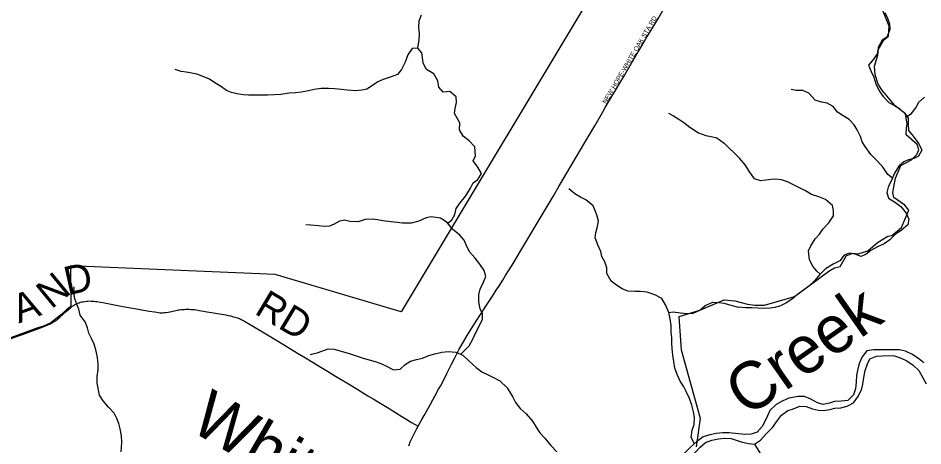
# Model space of a CAD drawing. Extents: x 1451455 to 1749751, y 218250 to 574981.
# Drawn here: x 1570249 to 1579778, y 367778 to 372287 of the extents above; entities that cross this region are included whole.
import ezdxf

# ---------------------------------------------------------------- set-up
doc = ezdxf.new("R2010")
doc.units = 0
for name, color, linetype in [('GM_X_City_Street', 7, 'Continuous'), ('GM_X_City_Street_Text', 7, 'Continuous'), ('GM_X_Corporation', 7, 'Continuous'), ('GM_X_County_Road', 7, 'Continuous'), ('GM_X_County_Road_Text', 7, 'Continuous'), ('GM_X_Major_River', 7, 'Continuous'), ('GM_X_Major_River_Text', 7, 'Continuous'), ('GM_X_Minor_River', 7, 'Continuous'), ('GM_X_Township', 7, 'Continuous')]:
    doc.layers.add(name, color=color, linetype=linetype)

msp = doc.modelspace()

# ---------------------------------------------------------------- linework, layer by layer
at = {"layer": 'GM_X_City_Street'}
msp.add_lwpolyline([(1576403.2, 371290.5), (1576433.5, 371342.8), (1576627.5, 371672), (1576696.7, 371787.7), (1576769.1, 371911.8), (1576787.8, 371943.4), (1576847.5, 372043.6), (1576865.4, 372074), (1576933.3, 372185.8), (1576996.4, 372293.8), (1577086.1, 372448.5), (1577119, 372505.8), (1577147.9, 372555.6), (1577156.9, 372571.7), (1577177.1, 372609.6), (1577191.9, 372638.4), (1577203.5, 372664.9), (1577210.3, 372682.1), (1577217.3, 372700.6), (1577222.8, 372716.8), (1577226.9, 372730.2), (1577232.6, 372751.3), (1577236.4, 372767), (1577237.7, 372774.9)], dxfattribs=at)
at = {"layer": 'GM_X_Corporation'}
msp.add_lwpolyline([(1569813.3, 375725.6), (1574235.6, 374596.8), (1575127.2, 374369.7), (1576500.8, 372892.2), (1574283.4, 369191.6), (1572956.4, 369585.2), (1570803, 369677.4), (1570805.4, 369246.2), (1570764.4, 369217.1), (1570697.9, 369158.2), (1570643.5, 369113.5), (1570593, 369073.7), (1570517.3, 369040.5), (1570456.2, 369021.9), (1569964.8, 368843.9)], dxfattribs=at)
at = {"layer": 'GM_X_County_Road'}
for points in [[(1574462.3, 367985.2), (1574505.6, 368063), (1574525.2, 368097.7), (1574570.5, 368180.2), (1574638.9, 368303.4), (1574678, 368374.8), (1574696.7, 368409.4), (1574732.3, 368475.8), (1574765.5, 368542.6), (1574793.4, 368598.8), (1574813.3, 368639.1), (1574844.2, 368700.5), (1574891.2, 368790.3), (1574928.3, 368856.2), (1574990.6, 368960.4), (1575049.4, 369055.3), (1575111.7, 369151.8), (1575183.6, 369261.5), (1575238.7, 369347), (1575261.6, 369382.8), (1575284.3, 369418.8), (1575311.9, 369459.2), (1575353.4, 369525.4), (1575382.7, 369572.6), (1575414.1, 369622.4), (1575452.2, 369683.5), (1575484.7, 369736.6), (1575534.9, 369821.1), (1575587, 369908.4), (1575618.5, 369962.2), (1575726.1, 370142.4), (1575884.4, 370407.5), (1575945.6, 370511.7), (1576218.6, 370976.2), (1576323.4, 371152.7), (1576403.2, 371290.5)], [(1570804.1, 369237.6), (1570819.8, 369249.3), (1570833.2, 369258.1), (1570844.5, 369265), (1570855.8, 369271.5), (1570866.2, 369276.7), (1570878.8, 369282.4), (1570891.8, 369287.5), (1570904.4, 369291.5), (1570920.9, 369295.8), (1570933.9, 369298.4), (1570951.3, 369301.5), (1570968.6, 369303.6), (1570984.3, 369304.9), (1571003.4, 369305.8), (1571020.7, 369305.4), (1571034.6, 369304.5), (1571048.5, 369303.2), (1571064.1, 369301.5), (1571082.8, 369299), (1571113.6, 369293.7), (1571140.8, 369288.2), (1571246.9, 369267.5), (1571353.2, 369247.7), (1571495.2, 369222.2), (1571608.2, 369202.1), (1571711.8, 369186.5), (1571728.2, 369184.3), (1571743.8, 369182.5), (1571759.4, 369181.7), (1571773.7, 369182.1), (1571787.2, 369183), (1571804.6, 369184.7), (1571830.2, 369189), (1571866.3, 369195.8), (1571911.2, 369205), (1571926.1, 369208.6), (1571937.4, 369210.7), (1571948.7, 369212.9), (1571965.2, 369215.1), (1571980.4, 369216.4), (1571996.8, 369217.2), (1572012.5, 369217.7), (1572049.8, 369218.1), (1572068.9, 369217.2), (1572089.3, 369216), (1572107.1, 369214.2), (1572127.9, 369211.7), (1572160.4, 369206.9), (1572241.2, 369192.6), (1572328.3, 369176.8), (1572438.4, 369158.7), (1572463.2, 369153.2), (1572486.8, 369148.2), (1572507.5, 369142.8), (1572531.3, 369136.2), (1572558.7, 369127.2), (1572581.2, 369119.4), (1572599.7, 369111.4), (1572635.3, 369093.9), (1572695, 369059.5), (1572858.1, 368961.1), (1572947.6, 368906.3), (1573045.4, 368846.4), (1573192.4, 368757.4), (1573276.5, 368706.2), (1573357.3, 368657.6), (1573421.5, 368618.5), (1573507.5, 368565.6), (1573592.5, 368514.4), (1573712.2, 368441.5), (1573827.2, 368372.3), (1573933.9, 368307.9), (1573987, 368275.4), (1574087.9, 368214.4), (1574158, 368172.1), (1574292.1, 368089.5), (1574344.3, 368056.9), (1574393, 368025.6), (1574462.3, 367985.2)], [(1569197.9, 368559.3), (1569312.5, 368602.7), (1569474, 368662.2), (1569668.2, 368732.7), (1569760.2, 368765.7), (1569849.6, 368796.9), (1570107.5, 368887.2), (1570335.7, 368967.9), (1570512.8, 369033.9), (1570556.2, 369051.3), (1570588.4, 369066), (1570604, 369073.8), (1570622.2, 369084.2), (1570643.1, 369098.1), (1570667.3, 369116.4), (1570690.6, 369136.4), (1570721.2, 369163.2), (1570759.4, 369198.8), (1570778.9, 369216.4), (1570804.1, 369237.6)], [(1574363.8, 367778.2), (1574370.3, 367796.1), (1574375.9, 367810.3), (1574379.9, 367820.3), (1574385.8, 367834.3), (1574396.3, 367857), (1574407.6, 367879.2), (1574422.1, 367907.2), (1574446.1, 367954.5), (1574462.3, 367985.2)]]:
    msp.add_lwpolyline(points, dxfattribs=at)
at = {"layer": 'GM_X_Major_River'}
for points in [[(1579787, 368655.3), (1579735.6, 368696.2), (1579670.2, 368741.3), (1579596.6, 368776.5), (1579532.7, 368789.4), (1579458.6, 368792.5), (1579388.5, 368791.6), (1579322.4, 368792.6), (1579256.3, 368791.6), (1579188.1, 368780.6), (1579137.1, 368717.2), (1579105.9, 368645.5), (1579090.8, 368573.6), (1579078, 368519.7), (1579075, 368453.6), (1579069.9, 368381.5), (1579046.9, 368317.8), (1578987.9, 368256.5), (1578917.7, 368249.5), (1578845.5, 368246.6), (1578795.2, 368229.3), (1578728.9, 368216.3), (1578667, 368231.3), (1578597.5, 368270.4), (1578531.8, 368297.4), (1578465.8, 368298.4), (1578365.3, 368279.9), (1578294.8, 368248.9), (1578234.1, 368213.7), (1578167.1, 368150.6), (1578140.2, 368096.9), (1578113.3, 368037.2), (1578086.4, 367981.5), (1578033.5, 367924.1), (1577971, 367901), (1577902.9, 367898), (1577737.7, 367914.6)], [(1577758.6, 367856.2), (1577865.7, 367820.4), (1577941.6, 367805.3), (1578005.5, 367796.3), (1578066.2, 367837.5), (1578127.3, 367904.7), (1578192.5, 367973.8), (1578245.6, 368045.2), (1578290.5, 368102.6), (1578355.4, 368151.8), (1578405.7, 368167), (1578482.3, 368198), (1578548.3, 368193), (1578616, 368167.9), (1578679.9, 368154.9), (1578729.9, 368150.2), (1578798.2, 368163.2), (1578850.5, 368176.4), (1578914.6, 368179.5), (1578981, 368198.5), (1579045.6, 368233.6), (1579094.6, 368297), (1579129.8, 368370.6), (1579144.7, 368430.5), (1579157.8, 368500.5), (1579170.9, 368574.4), (1579194, 368644.2), (1579220.8, 368695.9), (1579289.3, 368723), (1579351.5, 368728), (1579423.7, 368731), (1579479.7, 368726.1), (1579549.4, 368703), (1579609.1, 368674), (1579674.5, 368629), (1579733.7, 368572), (1579774.7, 368501.2), (1579811.7, 368432.5)], [(1577737.7, 367914.6), (1577671.8, 367917.7), (1577599.8, 367911), (1577533.6, 367894.1), (1577463.3, 367873.3), (1577392.5, 367820.5), (1577329.6, 367765.6), (1577254.3, 367688.9), (1577205.3, 367631.7), (1577164.3, 367570.3), (1577101.1, 367501.4), (1577056.2, 367448.2), (1576983.2, 367385.4), (1576924.6, 367350.4), (1576799.3, 367222.2)], [(1576856.7, 367185.1), (1577021.7, 367306.7), (1577088.7, 367371.5), (1577143.8, 367432.6), (1577219, 367505.4), (1577263.9, 367560.6), (1577311.2, 367631.8), (1577380.5, 367708.7), (1577431.4, 367763.8), (1577490.2, 367814.8), (1577556.6, 367839.7), (1577626.7, 367854.5), (1577692.7, 367859.3), (1577758.6, 367856.2)]]:
    msp.add_lwpolyline(points, dxfattribs=at)
at = {"layer": 'GM_X_Minor_River'}
for points in [[(1574458.8, 371971.1), (1574474.2, 372056.9), (1574475.2, 372118.9), (1574470.4, 372191), (1574473.5, 372259), (1574496.5, 372322.6)], [(1579378.9, 372346), (1579406, 372285.6), (1579425.2, 372227.2), (1579430.4, 372167.1), (1579399.4, 372087.4), (1579349, 372054), (1579308, 371976.4), (1579303.3, 371922.3), (1579260.5, 371858.8), (1579205.7, 371791.4), (1579232.8, 371724.9), (1579259.9, 371662.5), (1579283, 371594.1), (1579318, 371521.5), (1579361.1, 371460.8), (1579418.2, 371398), (1579477.7, 371365.1), (1579533.3, 371332.4), (1579588.5, 371281.6), (1579623.8, 371231), (1579623, 371168.9), (1579626.1, 371102.8), (1579675.3, 371044), (1579736.1, 370963.1), (1579765.2, 370894.6), (1579732.4, 370831), (1579682.1, 370805.6), (1579628, 370792.2), (1579575.7, 370770.9), (1579523.2, 370727.5), (1579480.3, 370653.9), (1579449.4, 370584.2), (1579412.4, 370504.6), (1579397.7, 370448.7), (1579414.9, 370390.4), (1579490.2, 370343.3), (1579545.6, 370302.5), (1579600.6, 370231.7), (1579631.7, 370169.2), (1579618.9, 370107.2), (1579552.2, 370052), (1579485.7, 370006.8), (1579431, 369949.4), (1579368.5, 369908.2), (1579300.1, 369875), (1579229.7, 369835.9), (1579179.3, 369798.5), (1579127, 369773.1), (1579065.4, 369798), (1579001.6, 369810.8), (1578949.3, 369787.5), (1578902.6, 369730), (1578834.2, 369692.8), (1578753.7, 369645.8), (1578688.9, 369580.5), (1578638.1, 369519.1), (1578575.4, 369461.8)], [(1574774.4, 370125), (1574816.5, 370160.4), (1574849.4, 370217.9), (1574862.4, 370279.7), (1574903.3, 370341.1), (1574964.5, 370414.2), (1575013.7, 370495.4), (1575040.6, 370551), (1575091.1, 370586.2), (1575128.1, 370647.7), (1575089.3, 370716.3), (1575042.4, 370781.1), (1575065.3, 370836.8), (1575058.8, 370928.9), (1574999.9, 370991.9), (1574936.8, 371040.9), (1574898, 371107.6), (1574901.2, 371181.6), (1574846.9, 371282.5), (1574853.8, 371334.4), (1574864.8, 371396.3), (1574863.8, 371456.3), (1574794.8, 371511.5), (1574724.8, 371506.6), (1574681.7, 371559.3), (1574670.8, 371625.5), (1574628.1, 371698.2), (1574551, 371745.5), (1574514.1, 371810.1), (1574509.1, 371870.2), (1574501.9, 371920.3), (1574458.8, 371971.1), (1574400.8, 371966), (1574353.7, 371898.7), (1574324.5, 371823.1), (1574287.3, 371745.7), (1574246.5, 371692.3), (1574166.1, 371663.6), (1574093.8, 371638.7), (1574039.5, 371613.6), (1573972.9, 371570.6), (1573920.4, 371539.4), (1573870.3, 371528.2), (1573802.3, 371521.3), (1573716.5, 371526.7), (1573656.7, 371533.6), (1573585, 371542.8), (1573519.1, 371545.8), (1573441.2, 371543.1), (1573367.1, 371534.3), (1573307, 371521.2), (1573232.8, 371506.4), (1573172.8, 371499.4), (1573104.8, 371494.4), (1573016.7, 371481.8), (1572950.8, 371478.9), (1572874.8, 371476.1), (1572814.9, 371475.1), (1572743, 371474.2), (1572675.1, 371475.3), (1572623.2, 371478.1), (1572551.5, 371487.3), (1572497.8, 371504.1), (1572444.2, 371523), (1572391, 371563.9), (1572321.7, 371605), (1572264.5, 371643.9), (1572187, 371673.2), (1572131.5, 371696.1), (1572079.7, 371706.9), (1572020, 371715.9), (1571968.2, 371724.7), (1571904.6, 371745.7)], [(1579457.1, 370601.6), (1579410.2, 370638.8), (1579361.2, 370711.6), (1579300.1, 370778.5), (1579231.1, 370849.5), (1579170.3, 370932.5), (1579139, 370982.9), (1579119.8, 371039.3), (1579084.7, 371107.8), (1579053.5, 371162.3), (1579002.3, 371217.1), (1578936.8, 371256), (1578877.4, 371296.9), (1578832.2, 371353.5), (1578768.8, 371390.4), (1578711, 371401.2), (1578643.3, 371422.1), (1578578.4, 371497.1), (1578514.8, 371524), (1578444.9, 371522.9), (1578391.1, 371533.6)], [(1579610.3, 371250.4), (1579656.5, 371282.7), (1579703.2, 371342.2), (1579735.9, 371399.8), (1579796.6, 371453.1)], [(1577097.8, 371286.5), (1577153.3, 371257.6), (1577208.6, 371220.7), (1577260, 371185.9), (1577325.1, 371136.8), (1577414, 371077.3), (1577491.4, 371048.1), (1577549.1, 371039.2), (1577608.8, 371026.2), (1577683.8, 370967), (1577846, 370809.5)], [(1578696, 369587.7), (1578661.4, 369620.9), (1578618.2, 369673.6), (1578583.1, 369740.1), (1578572.3, 369832.4), (1578597, 369888.2), (1578641.9, 369959.8), (1578690.6, 370011.2), (1578725.2, 370062.8), (1578788, 370128.1), (1578837, 370203.6), (1578837.7, 370259.7), (1578824.4, 370311.9), (1578753.3, 370375), (1578683.8, 370401.9), (1578604.2, 370429), (1578542.8, 370465.9), (1578479.3, 370498.8), (1578352.2, 370560.5), (1578290.6, 370581.3), (1578230.7, 370588.1), (1578178.7, 370586.8), (1578124.7, 370577.5), (1578072.7, 370572.2), (1578005, 370591.1), (1577948.1, 370672), (1577905.1, 370740.6), (1577846, 370809.5)], [(1577371.2, 367801.9), (1577339.2, 367866.9), (1577348.4, 367942.8), (1577369.4, 368002.5), (1577372.7, 368080.4), (1577363.6, 368138.6), (1577344.8, 368209), (1577320, 368279.4), (1577283.3, 368352), (1577256.2, 368408.5), (1577223.1, 368459), (1577192.2, 368523.6), (1577165.5, 368596), (1577154.7, 368668.2), (1577143.8, 368736.4), (1577138.9, 368804.6), (1577135.8, 368860.6), (1577132.8, 368918.7), (1577127.8, 368978.8), (1577127, 369048.9), (1577118.1, 369117), (1577103.2, 369183.3), (1577068.6, 369265.9), (1577029.7, 369330.6), (1576954.5, 369371.8), (1576875, 369397.1), (1576805.3, 369406.2), (1576743.4, 369405.2), (1576669.6, 369410.4), (1576610, 369433.3), (1576550.7, 369472.3), (1576493.5, 369515.3), (1576450.9, 369596), (1576447.9, 369654), (1576429, 369718.4), (1576395.9, 369773), (1576384.8, 369827.1), (1576356, 369895.6), (1576327.2, 369970.1), (1576334.2, 370026.1), (1576347, 370077.9), (1576360.1, 370147.7), (1576349, 370197.9), (1576331.8, 370248.2), (1576304.8, 370308.7), (1576230, 370369.9), (1576172.5, 370400.8), (1576113.2, 370433.8), (1576048.2, 370488.9)], [(1574911.5, 368743.5), (1574941.5, 368773.7), (1574998.4, 368834.8), (1575035.4, 368896.2), (1575074.7, 368979.6), (1575105.7, 369041.2), (1575140.8, 369114.7), (1575141.7, 369168.7), (1575114.6, 369223.1), (1575099.8, 369295.4), (1575101.1, 369369.4), (1575114.1, 369431.2), (1575149.2, 369502.7), (1575176.2, 369564.3), (1575159.2, 369626.6), (1575110.4, 369693.5), (1575061.5, 369758.3), (1575002.7, 369825.2), (1574967.9, 369897.8), (1574948.8, 369948.2), (1574899.7, 369999), (1574822.9, 370062.2), (1574768.1, 370133.1), (1574696.9, 370178.3), (1574601.3, 370191.8), (1574545.2, 370182.7), (1574468.7, 370145.9), (1574390.5, 370127.2), (1574298.7, 370126.6), (1574242.8, 370133.5), (1574177.1, 370140.6), (1574091.3, 370150), (1574033.6, 370160.9), (1573977.8, 370167.8), (1573905.8, 370163), (1573829.5, 370140.2), (1573743.7, 370143.5), (1573686, 370156.5), (1573633.9, 370145.3), (1573579.4, 370114.1), (1573529.2, 370094.9), (1573473.2, 370091.8), (1573413.4, 370096.8), (1573333.6, 370104.1), (1573279.8, 370108.9)], [(1571335.1, 367716.7), (1571342.7, 367814.6), (1571337.8, 367884.7), (1571323, 367957), (1571310, 368015.3), (1571290.9, 368067.6), (1571261.9, 368124.1), (1571203, 368185.1), (1571144.1, 368252), (1571107.2, 368314.7), (1571081.3, 368441.1), (1571082.5, 368509.2), (1571091.6, 368581), (1571092.6, 368639.1), (1571085.8, 368709.2), (1571072.9, 368777.5), (1571050.2, 368851.9), (1571027, 368902.2), (1570996.1, 368966.8), (1570979, 369021.1), (1570956.2, 369087.5), (1570903.4, 369156.4), (1570888.4, 369218.6), (1570869.3, 369273), (1570848.3, 369329.3), (1570837.4, 369393.5), (1570838.4, 369453.6)], [(1578575.4, 369461.8), (1578520.9, 369418.4), (1578458.3, 369373.2), (1578407.8, 369331.8), (1578341.3, 369284.6), (1578278.9, 369253.3), (1578218.8, 369238.1), (1578168.7, 369228.7), (1578104.7, 369225.5), (1578042.9, 369230.4), (1577977, 369233.2), (1577909, 369232.1), (1577833.2, 369241.1)], [(1577103.2, 369183.3), (1577149.3, 369192.6), (1577225, 369179.4), (1577294.8, 369172.3), (1577358.8, 369177.2), (1577429.2, 369210.1), (1577485.9, 369259.3), (1577564.4, 369294), (1577628.2, 369291), (1577682, 369282.1), (1577833.2, 369241.1)], [(1573325.2, 368741.5), (1573399.4, 368758.3), (1573449.6, 368777.5), (1573515.9, 368800.5), (1573577.8, 368799.5), (1573639.4, 368780.5), (1573726.9, 368755.1), (1573820.2, 368723.5), (1573881.8, 368704.5), (1573947.4, 368685.5), (1574009, 368668.5), (1574070.6, 368645.5), (1574128.1, 368618.6), (1574201.3, 368579.4), (1574273.4, 368588.2), (1574324.1, 368637.5), (1574382.6, 368670.5), (1574446.7, 368687.5), (1574508.9, 368702.5), (1574573.3, 368729.5), (1574639.5, 368750.5), (1574711.7, 368765.3), (1574777.7, 368772.3), (1574859.5, 368767), (1574932.8, 368733.8), (1574997.8, 368674.7), (1575072.5, 368603.5), (1575133.7, 368558.5), (1575199.1, 368527.4), (1575254.5, 368498.5), (1575321.9, 368465.4), (1575398.5, 368390.1), (1575458.8, 368291.1), (1575487.8, 368234.6), (1575536.8, 368173.8), (1575599.7, 368116.8), (1575668.3, 368037.6), (1575705.3, 367977), (1575744.2, 367916.4), (1575795.3, 367861.5), (1575859.9, 367784.5), (1575922.7, 367715.4)], [(1578005.5, 367796.3), (1578425.5, 367105.8)]]:
    msp.add_lwpolyline(points, dxfattribs=at)
at = {"layer": 'GM_X_Township'}
msp.add_lwpolyline([(1577393.4, 367767.6), (1577437.5, 368065.9), (1577237, 368786.2), (1577210.9, 369141.3), (1577427.5, 369210.3), (1577686.3, 369317.8), (1577796.4, 369308.5), (1577932.5, 369273.5), (1578009.5, 369262.7), (1578111.4, 369262), (1578426.7, 369354.4), (1578788.1, 369620.2), (1578848.2, 369654.3), (1578908.3, 369670.3), (1578972.4, 369786.5), (1579042.6, 369810.6), (1579094.7, 369802.5), (1579196.9, 369834.6), (1579301.1, 369922.5), (1579408.8, 369988.4), (1579451.1, 369996.1), (1579553.5, 370081.1), (1579631.7, 370263.4), (1579587.6, 370315.5), (1579473.4, 370395.6), (1579461.4, 370449.7), (1579489.9, 370599.2), (1579545.5, 370732.3), (1579657.7, 370794.4), (1579715.8, 370848.5), (1579735.9, 370898.6), (1579717.8, 370954.7), (1579601.6, 371054.9), (1579604.4, 371130.8), (1579613.7, 371169.1), (1579593.6, 371277.3), (1579485.4, 371363.4), (1579347.2, 371531.8), (1579307.1, 371589.9), (1579273.9, 371689.7), (1579269, 371780.2), (1579305.1, 371896.4), (1579303.1, 371946.5), (1579367.2, 372056.7), (1579417.3, 372096.8), (1579421.3, 372203), (1579329.1, 372433.4)], dxfattribs=at)
msp.add_lwpolyline([(1577393.4, 367767.6), (1577437.5, 368065.9), (1577237, 368786.2), (1577210.9, 369141.3), (1577427.5, 369210.3), (1577686.3, 369317.8), (1577796.4, 369308.5), (1577932.5, 369273.5), (1578009.5, 369262.7), (1578111.4, 369262), (1578426.7, 369354.4), (1578788.1, 369620.2), (1578848.2, 369654.3), (1578908.3, 369670.3), (1578972.4, 369786.5), (1579042.6, 369810.6), (1579094.7, 369802.5), (1579196.9, 369834.6), (1579301.1, 369922.5), (1579408.8, 369988.4), (1579451.1, 369996.1), (1579553.5, 370081.1), (1579631.7, 370263.4), (1579587.6, 370315.5), (1579473.4, 370395.6), (1579461.4, 370449.7), (1579489.9, 370599.2), (1579545.5, 370732.3), (1579657.7, 370794.4), (1579715.8, 370848.5), (1579735.9, 370898.6), (1579717.8, 370954.7), (1579601.6, 371054.9), (1579604.4, 371130.8), (1579613.7, 371169.1), (1579593.6, 371277.3), (1579485.4, 371363.4), (1579347.2, 371531.8), (1579307.1, 371589.9), (1579273.9, 371689.7), (1579269, 371780.2), (1579305.1, 371896.4), (1579303.1, 371946.5), (1579367.2, 372056.7), (1579417.3, 372096.8), (1579421.3, 372203), (1579329.1, 372433.4)], dxfattribs=at)

# ---------------------------------------------------------------- texts
at = {"layer": 'GM_X_City_Street_Text'}
msp.add_text('NEW HOPE-WHITE OAK STA RD', height=50, rotation=59.36678, dxfattribs=at).set_placement((1576441.4, 371378.8))
at = {"layer": 'GM_X_County_Road_Text'}
for s, rotation, p in [('D', 12.58847, (1570771, 369364)), ('N', 39.31448, (1570599.7, 369212.8)), ('A', 20.02863, (1570256.3, 369068.1)), ('RD', 329.03511, (1572727.3, 369177.7))]:
    msp.add_text(s, height=300, rotation=rotation, dxfattribs=at).set_placement(p)
at = {"layer": 'GM_X_Major_River_Text'}
for s, height, rotation, p in [('Creek', 500.03, 35.00637, (1577926.7, 368072.1)), ('White', 500.02, 329.99559, (1572039.8, 367953.3))]:
    msp.add_text(s, height=height, rotation=rotation, dxfattribs=at).set_placement(p)

doc.saveas('drawing.dxf')
